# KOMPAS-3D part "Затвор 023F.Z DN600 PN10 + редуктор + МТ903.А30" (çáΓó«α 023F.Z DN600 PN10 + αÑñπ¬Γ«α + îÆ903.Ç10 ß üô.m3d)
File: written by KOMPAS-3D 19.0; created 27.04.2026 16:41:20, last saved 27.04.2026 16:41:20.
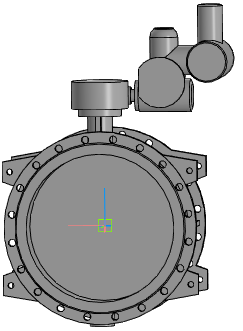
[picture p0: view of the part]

Document properties: Полное имя файла: ..\..\Затвор 023F.Z DN400-DN1600 + редуктор + МТ903\Затвор 023F.Z DN600 PN10 + редуктор + МТ903.А10 с БУ.a3d

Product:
- Part/product: Затвор 023F.Z DN600 PN10 + редуктор + МТ903.А30
    Масса: 513.986

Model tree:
1. Операция без истории:1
